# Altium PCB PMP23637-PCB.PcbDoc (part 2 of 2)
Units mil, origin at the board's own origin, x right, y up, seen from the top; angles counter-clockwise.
Board outline 3000 x 2000 mil, 6 copper layers (Top Layer, Layer 2, Signal Layer 3, Signal Layer 4, Layer 5, Bottom Layer), stack 61.712 mil thick; 143 components, 52 nets, 318 pads, 582 vias.
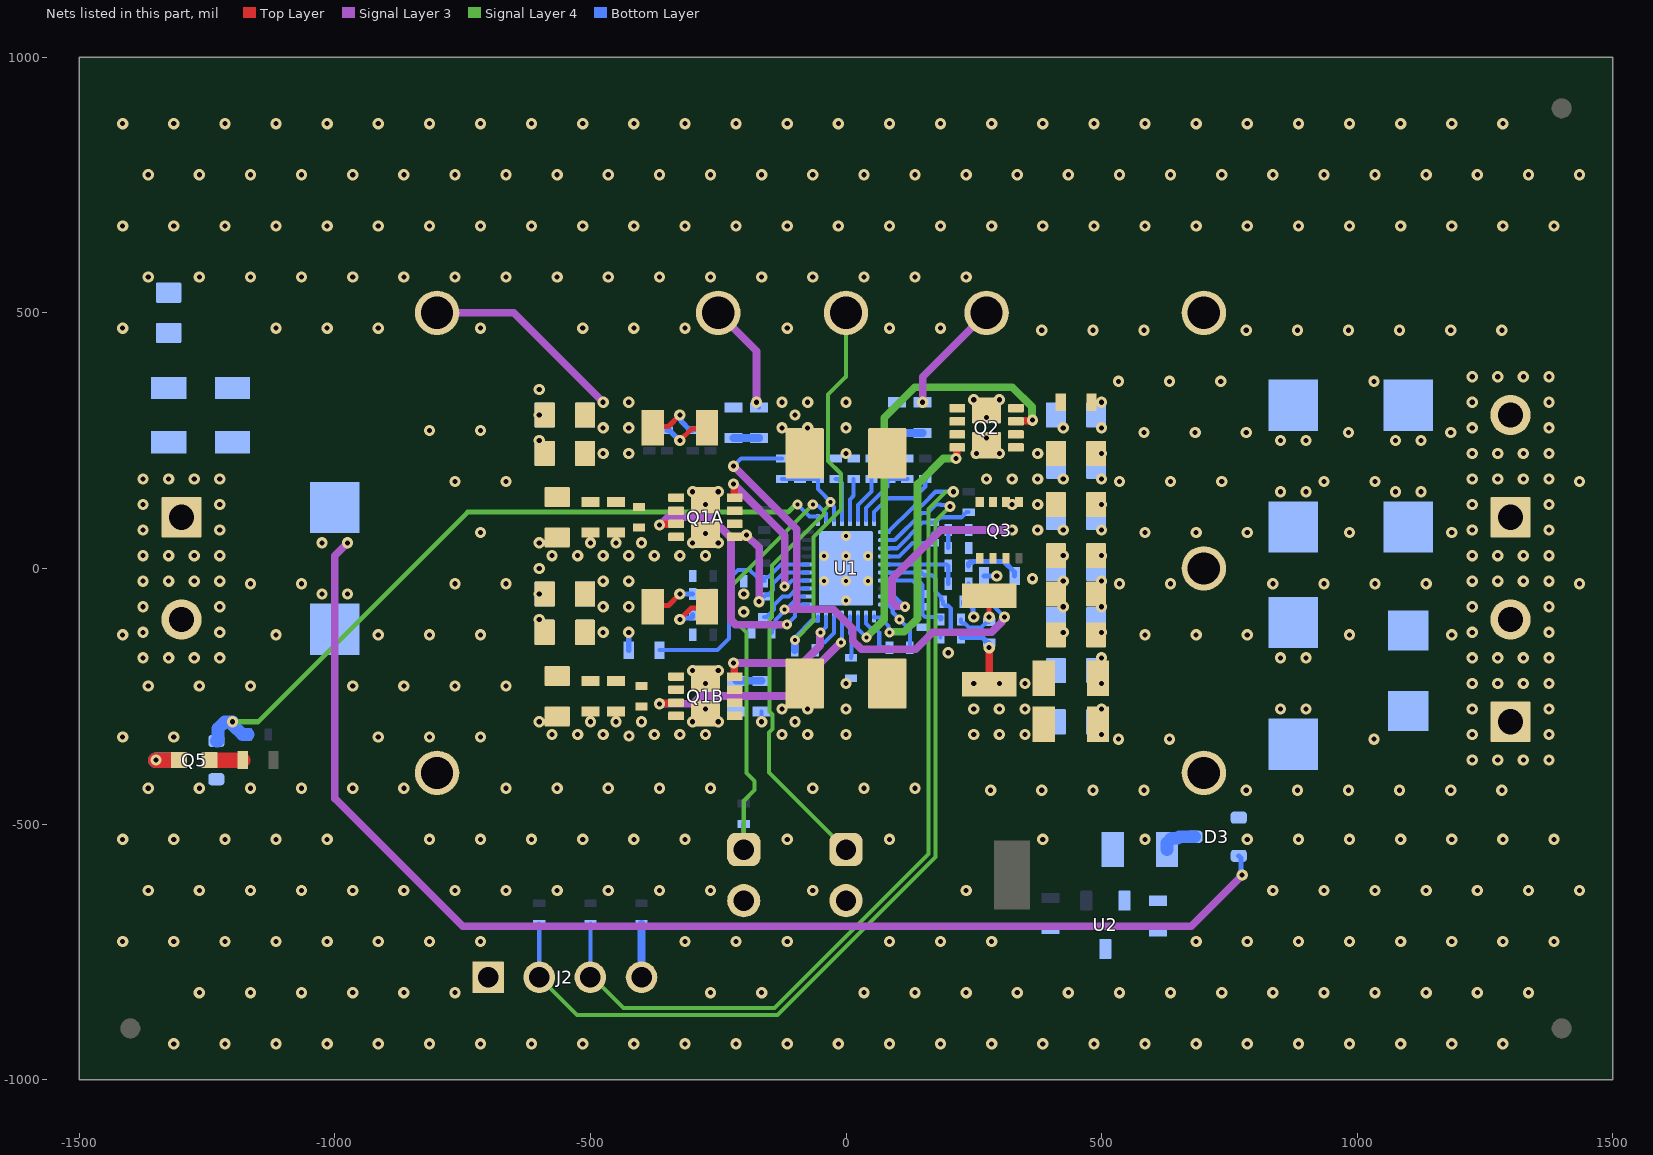
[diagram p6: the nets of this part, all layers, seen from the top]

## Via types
v1: diameter 22, hole 10, Top Layer to Bottom Layer, tented both sides, 560 vias
v2: diameter 19.68, hole 7.87, Top Layer to Bottom Layer, tented both sides, 22 vias

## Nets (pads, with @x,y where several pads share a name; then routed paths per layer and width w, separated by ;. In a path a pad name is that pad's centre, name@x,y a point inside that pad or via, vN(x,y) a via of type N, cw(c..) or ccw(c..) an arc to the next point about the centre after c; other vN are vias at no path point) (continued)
BTST1_A: C48.1 U1.3 | length 113.6
  Bottom Layer w8: C48.1@-160,-95 -155.5,-95 -141,-80.5 -141,-71.3 -124.54,-54.84 -111.78,-54.84 -96.31,-39.37 U1.3@-74.8,-39.37
BTST1_B: C44.1 U1.34 | length 85
  Bottom Layer w8: C44.1@-60,-160 -60,-155.5 -49.34,-144.84 -41.78,-144.84 -23.62,-126.68 U1.34@-23.62,-94.49
BTST2: C39.1 U1.30 | length 93.1
  Bottom Layer w8: U1.30@39.37,-94.49 39.43,-94.55 39.43,-107.54 48.19,-116.3 56.3,-116.3 65,-125 65,-150.31 69.69,-155 C39.1@85,-155
CELL_BATPRESZ: R6.2 R7.1 U1.23 | length 161.4
  Bottom Layer w8: U1.23@74.8,7.87 197.13,7.87 R6.2@200,5 R7.1@200,-30
CHRG_OK: Q5.1 R28.2 U1.11 | length 1448
  Signal Layer 4 w10: v1(-1200,-300) -1150,-300 -740,110 -291.11,110 -284.11,103 -265.89,103 -258.89,110 -113.25,110 -98.25,125 v2(-95,125)
  Bottom Layer w8: v2(-95,125) -71.18,101.18 -55.18,101.18 -55.12,101.12 U1.11@-55.12,94.49
  Bottom Layer w25: Q5.1@-1231.69,-337.6 -1229.13,-337.6 -1228.44,-336.91 -1228.44,-313.44 -1215,-300 v1(-1200,-300) -1200,-305.86 -1180.86,-325 R28.2@-1170,-325
CMPIN_TR: R4.2 R5.2 R10.2 U1.22 | length 191.9
  Bottom Layer w8: U1.22@74.8,23.62 103.62,23.62 130,50 R10.2@170,50 170,67.81 174.69,72.5 197.5,72.5 R4.2@200,75 R5.2@200,40
CMPOUT: R3.1 R10.1 U1.21 | length 194.5
  Bottom Layer w8: U1.21@74.8,39.37 99.37,39.37 150,90 174.5,90 184.5,100 225.5,100 235.5,110 R3.1@240,110
EN_OTG: JP1.1 R17.1 U1.12 | length 864.9
  Signal Layer 4 w8: JP1.1@-200,-550 -200,-454.7 -179,-433.7 -179,-416.3 -195,-400.3 -195,-125 -225,-95 -225,-35 v2(-65,125)
  Bottom Layer w8: JP1.1@-200,-550 R17.1@-200,-500 ; v2(-65,125) -62.32,122.32 -54.21,122.32 -39.43,107.54 -39.43,94.55 U1.12@-39.37,94.49
HIDRV1_A: Q1A.8 U1.4 | length 317.8
  Top Layer w15: v1(-220,165) -218.86,163.86 -218.86,139.15 -218.09,138.39 Q1A.8@-217.72,138.39
  Signal Layer 3 w15: v1@-219.1,164.1 -120,65 v2(-120,-35)
  Bottom Layer w8: v2(-120,-35) -116.84,-35 -105.46,-23.62 U1.4@-74.8,-23.62
HIDRV1_B: Q1B.8 U1.35 | length 272.2
  Top Layer w15: v1(-220,-185) -218.86,-186.14 -218.86,-210.85 -218.09,-211.61 Q1B.8@-217.72,-211.61
  Signal Layer 3 w15: v1(-220,-185) -85,-185 -50.9,-150.9 -50.9,-125.9 v2(-50,-125)
  Bottom Layer w8: v2(-50,-125) -39.37,-114.37 U1.35@-39.37,-94.49
HIDRV2: Q2.8 U1.29 | length 497.5
  Top Layer w15: v1(215,215) 216.34,216.34 216.34,235.85 217.11,236.61 Q2.8@217.72,236.61
  Signal Layer 4 w15: v2(85,-125) 85.9,-124.1 113.91,-124.1 140,-98.01 140,165 190,215 v1(215,215)
  Bottom Layer w8: U1.29@55.12,-94.49 55.12,-96.37 55.18,-96.43 66.43,-96.43 82.76,-112.76 82.76,-122.76 v2(85,-125)
IADPT: C43.1 U1.14 | length 88.2
  Bottom Layer w8: C43.1@-20,175 -15.5,175 -7.87,167.37 U1.14@-7.87,94.49
IBAT: C41.1 U1.15 | length 83.5
  Bottom Layer w8: U1.15@7.87,94.49 7.87,135.01 15,142.14 C41.1@15,175
ILIM_HIZ: C45.1 JP2.1 R15.1 R16.2 U1.13 | length 961.2
  Signal Layer 4 w8: v2(-30.14,130.16) -30.14,127 -43.42,113.72 -43.42,106.89 -145,5.3 -145,-95.3 -150,-100.3 -150,-279.7 -144,-285.7 -144,-314.3 -151,-321.3 -151,-399 JP2.1@0,-550
  Bottom Layer w8: R16.2@-125,175 R15.1@-90,175 C45.1@-55,175 -55,155.02 -27.91,127.92 -27.91,124.76 -23.62,120.48 U1.13@-23.62,94.49
LODRV1_A: Q1A.3 U1.1 | length 533.5
  Top Layer w15: v1(-365,85) -363.56,86.44 -333.05,86.44 Q1A.3@-332.28,87.2
  Signal Layer 3 w15: v1(-365,85) -363.73,85 -348.73,100 -265,100 -225,60 -225,-101.21 -216.21,-110 v2(-115,-110)
  Bottom Layer w8: v2(-115,-110) -99.38,-94.38 -99.38,-84.38 -85.87,-70.87 U1.1@-74.8,-70.87
LODRV1_B: Q1B.3 U1.33 | length 489.7
  Top Layer w15: v1(-365,-265) -363.56,-263.56 -333.05,-263.56 Q1B.3@-332.28,-262.8
  Signal Layer 3 w15: v1(-365,-265) -299.65,-265 -284.15,-249.5 -114.5,-249.5 v2(-10,-145)
  Bottom Layer w8: v2(-10,-145) -7.87,-142.87 U1.33@-7.87,-94.49
LODRV2: Q2.3 U1.31 | length 881.4
  Top Layer w15: Q2.3@332.28,287.8 333.05,288.56 361.67,288.56 363.11,290 v1(365,290)
  Signal Layer 4 w15: v2(40,-135) 75,-100 75,295 134.5,354.5 325.5,354.5 363.81,316.19 363.81,291.19 v1(365,290)
  Bottom Layer w8: U1.31@23.62,-94.49 23.62,-118.62 v2(40,-135)
MODE: R14.2 U1.16 | length 91.4
  Bottom Layer w8: U1.16@23.62,94.49 23.62,123.71 50,150.09 R14.2@50,175
NetC6_1: C6.1 C8.1 C10.1 C12.1 Q1B.1 Q1B.2 Q1B.9 R22.2 RAC_B.2 | length 95.3
  Top Layer w10: v1(-325,-100) -302.65,-77.65 -274.5,-77.65 RAC_B.2@-271.85,-75
  Bottom Layer w10: v1(-325,-100) -321.75,-100 -318.75,-97 -302.5,-97 -300,-94.5 R22.2@-300,-90
  other v1: -275,-225 -300,-200 -250,-200
NetC24_2: C24.2 R2.1 U2.2
NetC36_2: C36.2 R13.2 | length 50
  Bottom Layer w15: R13.2@100,265 C36.2@150,265
NetC49_2: C49.2 R18.2 | length 50
  Bottom Layer w15: R18.2@-220,255 C49.2@-170,255
NetC52_2: C52.2 R19.2 | length 50
  Bottom Layer w15: R19.2@-215,-220 -210,-220 C52.2@-165,-220
NetC62_1: C62.1 R29.1 R30.1
NetD1_1: D1.1 R1.1 | length 65.5
  Top Layer w30: D1.1@-1245.47,-375 R1.1@-1180,-375
NetD1_2: D1.2 Q5.3 | length 77.2
  Top Layer w30: v1(-1350,-375) D1.2@-1304.53,-375
  Bottom Layer w30: v1(-1350,-375) Q5.3@-1318.31,-375
NetD3_3: D3.3 R2.2 | length 71.4
  Bottom Layer w25: R2.2@628.15,-550 628.15,-537.2 637.3,-528.05 648.9,-528.05 651.95,-525 D3.3@681.69,-525
NetJ2_4: J2.4 R25.2 | length 105
  Bottom Layer w15: J2.4@-400,-800 R25.2@-400,-695
PGND: C1.2 C2.2 C3.2 C4.2 C5.2 C6.2 C7.2 C8.2 C9.2 C10.2 C11.2 C12.2 C13.2 C14.2 C15.2 C16.2 C17.2 C18.2 C19.2 C20.2 C21.2 C22.2 C23.2 C24.1 C25.2 C26.2 C27.2 C28.2 C29.2 C30.2 C31.2 C32.1 C33.2 C35.2 C38.2 C40.2 C41.2 C42.1 C43.2 C45.2 C50.2 C51.2 C53.2 C54.2 C55.2 C56.2 C57.2 C58.2 C59.2 C60.2 C61.2 C62.2 D2.2 J1.2 J2.1 J3.1 J4.2 JP1.2 JP2.2 Q1A.4 Q1A.10 Q1B.4 Q1B.10 Q2.4 Q2.10 Q5.2 R5.1 R6.1 R12.2 R13.1 R14.1 R15.2 R18.1 R19.1 TP2.1 TP9.1 U1.37 U2.3 | length 156.4
  Bottom Layer w10: C35.2@230,-65 230,-69.5 232.5,-72 242.29,-72 248.15,-77.86 248.15,-93.15 v1(250,-95) ; R6.1@240,5 240,9.5 242.5,12 247,12 248.5,13.5 309,13.5 330,-7.5 C33.2@330,-15
  other v1: -1315,-930 -1215,-930 -1115,-930 -1015,-930 -915,-930 -815,-930 -715,-930 -615,-930 -515,-930 -415,-930 -315,-930 -215,-930 -115,-930 -15,-930 85,-930 185,-930 285,-930 385,-930 485,-930 585,-930 685,-930 785,-930 885,-930 985,-930 1085,-930 1185,-930 1285,-930 -1265,-830 -1165,-830 -1065,-830 -965,-830 -865,-830 -765,-830 -265,-830 -165,-830 35,-830 135,-830 235,-830 335,-830 435,-830 535,-830 635,-830 735,-830 835,-830 935,-830 1035,-830 1135,-830 1235,-830 1335,-830 -1415,-730 -1315,-730 -1215,-730 -1115,-730 -1015,-730 -915,-730 -815,-730 -715,-730 -315,-730 -215,-730 -115,-730 85,-730 185,-730 285,-730 685,-730 785,-730 885,-730 985,-730 1085,-730 1185,-730 1285,-730 1385,-730 -1365,-630 -1265,-630 -1165,-630 -1065,-630 -965,-630 -865,-630 -765,-630 -665,-630 -565,-630 -465,-630 -365,-630 -265,-630 -65,-630 235,-630 835,-630 935,-630 1035,-630 1135,-630 1235,-630 1335,-630 1435,-630 -1415,-530 -1315,-530 -1215,-530 -1115,-530 -1015,-530 -815,-530 -715,-530 -615,-530 -515,-530 -415,-530 -315,-530 -115,-530 85,-530 385,-530 585,-530 785,-530 885,-530 985,-530 1085,-530 1185,-530 1285,-530 1385,-530 -1365,-430 -1265,-430 -1165,-430 -1065,-430 -965,-430 -865,-430 -665,-430 -565,-430 -465,-430 -365,-430 -265,-430 -65,-430 35,-430 135,-430 -1415,-330 -1315,-330 -915,-330 -815,-330 -715,-330 -424.33,-327.74 -575,-325 -525,-325 -475,-325 -375,-325 -325,-325 -275,-325 0,-325 500,-325 -600,-300 -500,-300 -450,-300 -400,-300 -300,-300 -250,-300 -275,-275 0,-275 500,-275 -1365,-230 -1265,-230 -1165,-230 -965,-230 -865,-230 -765,-230 -665,-230 0,-225 500,-225 -1375,-175 -1325,-175 -1275,-175 -1225,-175 500,-175 850,-175 900,-175 1225,-175 1275,-175 1325,-175 1375,-175 200,-165 -1415,-130 -1115,-130 -915,-130 -815,-130 -715,-130 585,-130 685,-130 785,-130 985,-130 1185,-130 -1375,-125 -1225,-125 500,-125 1225,-125 1375,-125 -600,-100 -200,-85 -1375,-75 -1225,-75 500,-75 1225,-75 1375,-75 -1025,-50 -975,-50 -600,-50 -200,-50 -1165,-30 -1065,-30 -765,-30 -665,-30 535,-30 635,-30 835,-30 935,-30 1035,-30 1135,-30 1435,-30 -1375,-25 -1325,-25 -1275,-25 -1225,-25 500,-25 1225,-25 1275,-25 1325,-25 1375,-25 365,-20 -600,0 -575,25 -525,25 -475,25 -425,25 -375,25 -325,25 -275,25 500,25 1225,25 1275,25 1325,25 1375,25 -600,50 -500,50 -450,50 -400,50 -300,50 -250,50 -275,68 -715,70 585,70 685,70 785,70 985,70 1185,70 500,75 1225,75 1375,75 500,125 1225,125 1375,125 850,150 900,150 1075,150 1125,150 -765,170 -665,170 535,170 635,170 735,170 935,170 1035,170 1435,170 500,175 1225,175 1275,175 1325,175 1375,175 0,225 500,225 -600,250 -815,270 -715,270 0,275 500,275 275,295 -600,300 0,325 500,325 250,330 300,330 -600,350 -1415,470 -1115,470 -1015,470 -915,470 -715,470 -515,470 -415,470 -315,470 -115,470 85,470 185,470 -1365,570 -1265,570 -1165,570 -1065,570 -965,570 -865,570 -765,570 -665,570 -565,570 -465,570 -365,570 -265,570 -165,570 -65,570 35,570 135,570 235,570 -1415,670 -1315,670 -1215,670 -1115,670 -1015,670 -915,670 -815,670 -715,670 -615,670 -515,670 -415,670 -315,670 -215,670 -115,670 -15,670 85,670 185,670 285,670 385,670 485,670 585,670 685,670 785,670 885,670 985,670 1085,670 1185,670 1285,670 1385,670 -1365,770 -1265,770 -1165,770 -1065,770 -965,770 -865,770 -765,770 -665,770 -565,770 -465,770 -365,770 -265,770 -165,770 -65,770 35,770 135,770 235,770 335,770 435,770 535,770 635,770 735,770 835,770 935,770 1035,770 1135,770 1235,770 1335,770 1435,770 -1415,870 -1315,870 -1215,870 -1115,870 -1015,870 -915,870 -815,870 -715,870 -615,870 -515,870 -415,870 -315,870 -215,870 -115,870 -15,870 85,870 185,870 285,870 385,870 485,870 585,870 685,870 785,870 885,870 985,870 1085,870 1185,870 1285,870
  other v2: 0,-62.99 -43.31,-24.61 0,-24.61 43.31,-24.61 -43.31,24.61 0,24.61 43.31,24.61 0,62.99
PROCHOT: R11.2 U1.18 | length 151.2
  Bottom Layer w8: U1.18@55.12,94.49 55.12,110.12 82.2,137.2 132.2,137.2 155,160 R11.2@155,175
PSYS: C40.1 R12.1 U1.17 | length 134.8
  Bottom Layer w8: U1.17@39.37,94.49 39.37,118.3 81.26,160.19 81.26,171.5 C40.1@84.76,175 ; C40.1@85,175 C40.1@84.76,175 ; R12.1@120,175 C40.1@84.76,175
REGNA: C51.1 R7.2 R16.1 U1.2 | length 1140.3
  Signal Layer 3 w15: v1(-220,200) -96.66,76.66 -96.66,-79.85 ; v2@-120,-79.31 v2(-120,-80) -96.8,-80 -25,-80 13.34,-118.34 13.34,-141.35 30.33,-158.34 136.66,-158.34 170,-125 284.65,-125 304.5,-105.15 304.5,-102.39 310,-96.89 v1(310,-95)
  Bottom Layer w8: v1(-220,200) -205,215 R16.1@-125,215 ; C51.1@-145,-125 -145,-120.5 -138,-113.5 -138,-100.84 -120,-82.84 v2(-120,-80) -117.14,-80 -92.32,-55.18 U1.2@-82.61,-55.18 ; R7.2@240,-30 240,-34.5 270.58,-65.08 280.08,-65.08 v1(310,-95)
REGNB: C42.2 U1.32 | length 82.2
  Bottom Layer w8: U1.32@7.87,-94.49 7.87,-127.67 9.84,-129.64 9.84,-137.9 10.93,-138.99 10.93,-171.5 10,-172.43 C42.2@10,-175
SCL: J2.2 R27.1 U1.20 | length 1895.1
  Signal Layer 4 w8: J2.2@-600,-800 -526.2,-873.8 -134,-873.8 175,-564.8 175,92.68 v1@203.13,120.81
  Bottom Layer w8: J2.2@-600,-800 R27.1@-600,-695 ; U1.20@74.8,55.12 74.87,55.18 95.38,55.18 148.51,108.31 159.52,108.31 176.21,125 184.66,125 185.64,124.02 200.98,124.02 v1(203.66,121.34)
SDA: J2.3 R26.1 U1.19 | length 1813.6
  Signal Layer 4 w8: J2.3@-500,-800 -495,-800 -435.2,-859.8 -139.8,-859.8 161,-559 161,116 194.24,149.24 209.24,149.24 v1(210,150)
  Bottom Layer w8: J2.3@-500,-800 R26.1@-500,-695 ; U1.19@82.61,70.93 131.88,120.2 134.88,123.2 148.41,123.2 175.21,150 v1(210,150)
SRN: C35.1 C37.2 R9.1 U1.24 | length 251.3
  Bottom Layer w8: U1.24@74.8,-7.87 147.87,-7.87 152.74,-12.74 167.74,-12.74 175,-20 175,-45 186.5,-56.5 186.5,-61.5 C35.1@190,-65 190,-69.5 193.5,-73 199.81,-73 205,-78.19 205,-121.81 199.81,-127 188.5,-127 185,-130.5 R9.1@185,-135
SRP: C37.1 C38.1 R8.1 U1.25 | length 180.8
  Bottom Layer w8: U1.25@74.8,-23.62 129.98,-23.62 133.86,-27.5 145.31,-27.5 150,-32.19 C37.1@150,-50 C38.1@150,-75 150,-90 155,-95 186.5,-95 186.5,-98.5 R8.1@185,-100
SW1_A: C48.2 C49.1 L1_A.1 Q1A.5 Q1A.6 Q1A.7 TP3.1 U1.5 | length 470.9
  Signal Layer 3 w15: TP3.1@-250,500 -175,425 v1(-175,325) ; v1(-195,65) -170,40 v1(-170,-65)
  Bottom Layer w8: v1(-175,325) -175,320 C49.1@-170,315 ; C48.2@-160,-55 -156.5,-51.5 -151.5,-51.5 -142.5,-42.5 -142.5,-29.44 -120.94,-7.87 U1.5@-74.8,-7.87
  other v1: -125,275 -75,275 -100,300 -125,325 -75,325
SW1_B: C44.2 C52.1 L1_B.1 Q1B.5 Q1B.6 Q1B.7 TP4.1 U1.36 | length 804.1
  Signal Layer 4 w8: v2(-100,-140) -63.23,-103.23 -63.23,61.77 -10.16,114.84 -10.16,185.16 -35,210 -35,340 0,375 TP4.1@0,500
  Bottom Layer w8: v1(-165,-300) C52.1@-165,-280 ; v2@-97.1,-132.1 -67.3,-102.3 -55.18,-102.3 -55.12,-102.24 U1.36@-55.12,-94.49
  Bottom Layer w15: C44.2@-100,-160 v2(-100,-140)
  other v1: -125,-325 -75,-325 -100,-300 -125,-275 -75,-275
SW2: C36.1 C39.2 L1_A.2 L1_B.2 Q2.5 Q2.6 Q2.7 TP5.1 U1.28 | length 336.2
  Signal Layer 3 w15: v1(150,325) 150,375 TP5.1@275,500
  Bottom Layer w8: U1.28@74.8,-70.87 82.55,-70.87 91.45,-79.77 91.45,-86.45 v2(105,-100) 125,-120 125,-154.89 C39.2@125,-155
VBAT: C13.1 C14.1 C23.1 C34.2 D2.1 D3.1 J4.1 R9.2 RSR.2 TP10.1 | length 131.7
  Top Layer w15: RSR.2@280,-226.61 v1(280,-155)
  Bottom Layer w10: R9.2@225,-135 267.14,-135 273,-140.86 273,-142.5 275.5,-145 C34.2@280,-145
  other v1: 283,-434 383,-434 483,-434 583,-434 783,-434 883,-434 983,-434 1083,-434 1183,-434 1283,-434 1225,-375 1275,-375 1325,-375 1375,-375 533,-334 633,-334 1033,-334 250,-325 300,-325 350,-325 1225,-325 1375,-325 250,-275 300,-275 350,-275 850,-275 900,-275 1225,-275 1375,-275 250,-225 300,-225 350,-225 1225,-225 1275,-225 1325,-225 1375,-225
VBAT_R: C33.1 C34.1 Q3.1 Q3.2 Q3.3 R8.2 RSR.1 | length 139.2
  Top Layer w10: v1(280,-95) RSR.1@280,-53.39
  Bottom Layer w8: R8.2@225,-100 225,-104.5 228.5,-108 233,-108 241,-116 264.5,-116 275.5,-105 C34.1@280,-105 ; v1@276.21,-95 v1(280,-95)
  Bottom Layer w10: C33.1@270,-15 v1(295,-15)
VBUS: C50.1 R20.1 U1.6 | length 447.4
  Bottom Layer w8: R20.1@-365,-160 -251.36,-160 -228.5,-137.14 -228.5,-19.86 -211.64,-3 -188.36,-3 -174.36,-17 -163.5,-17 C50.1@-160,-20.5 ; C50.1@-160,-25 C50.1@-160,-20.5 ; U1.6@-74.8,7.87 -127.13,7.87 -152,-17 -156.5,-17 C50.1@-160,-20.5
VIN: C1.1 C2.1 C3.1 C4.1 C57.1 C58.1 C59.1 C60.1 C61.1 D3.2 J1.1 R20.2 R21.2 R23.2 R29.2 R30.2 RAC_A.1 RAC_B.1 TP1.1 | length 3098.2
  Top Layer w10: RAC_B.1@-378.15,-75 -375.5,-72.35 -347.35,-72.35 v1(-325,-50) ; RAC_A.1@-378.15,275 -375.5,277.65 -347.35,277.65 v1(-325,300)
  Signal Layer 3 w15: v1(-975,50) -1000,25 -1000,-450 -750,-700 675,-700 v1(775,-600) ; TP1.1@-800,500 -650,500 v1(-475,325)
  Bottom Layer w10: R20.2@-425,-160 v1(-425,-125) ; v1(-325,-50) R21.2@-300,-50 ; v1(-325,300) -322.7,297.7 -322.7,288.2 -304.5,270 R23.2@-300,270 ; D3.2@768.31,-562.4 772.7,-566.8 772.7,-597.7 v1(775,-600)
  other v1: -475,-125 -475,-75 -425,-75 -475,-25 -425,-25 -1375,25 -1325,25 -1275,25 -1225,25 -1025,50 -1375,75 -1225,75 -1375,125 -1225,125 -1375,175 -1325,175 -1275,175 -1225,175 -475,225 -425,225 -475,275 -425,275 -425,325
VIN_R_A: C5.1 C7.1 C9.1 C11.1 Q1A.1 Q1A.2 Q1A.9 R24.2 RAC_A.2 | length 96.8
  Top Layer w10: v1(-325,250) -302.65,272.35 -274.5,272.35 RAC_A.2@-271.85,275
  Bottom Layer w10: R24.2@-350,270 -345.5,270 -325.5,250 v1(-325,250)
  other v1: -275,125 -300,150 -250,150
VSYS: C15.1 C16.1 C17.1 C18.1 C19.1 C20.1 C21.1 C22.1 C25.1 C26.1 C27.1 C28.1 C29.1 C30.1 C31.1 J3.2 Q2.1 Q2.2 Q2.9 Q3.5 Q3.6 Q3.7 Q3.8 R4.1 TP8.1 U1.27 | length 482
  Signal Layer 3 w15: v2(115,-75) 113.84,-73.84 98.79,-73.84 90,-65.05 90,-20 185,75 v1(325,75)
  Bottom Layer w8: U1.27@74.8,-55.12 95.12,-55.12 v2(115,-75)
  Bottom Layer w15: R4.1@240,75 v1(325,75)
  other v1: 425,-125 425,-75 425,-25 425,25 375,75 425,75 325,125 375,125 275,175 325,175 375,175 425,175 255,225 300,225 375,225 1225,225 1275,225 1325,225 1375,225 850,250 900,250 1075,250 1125,250 275,255 583,266 683,266 783,266 983,266 1183,266 425,275 1225,275 1375,275 1225,325 1375,325 533,366 633,366 733,366 1033,366 1225,375 1275,375 1325,375 1375,375 383,466 483,466 583,466 783,466 883,466 983,466 1083,466 1183,466 1283,466
pads on no net: FID1.1 FID2.1 FID3.1 FID4.1 FID5.1 FID6.1 H1.0 H2.0 H3.0 H4.0 LBL1.0 SH-JP1.0 SH-JP2.0

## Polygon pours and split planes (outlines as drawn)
VSYS on Top Layer "VSYS_L01_P183" (solid, pour order 183): 1425,575 350,575 350,200 1425,200
PGND on Top Layer "PGND_L01_P157" (solid, remove dead copper, pour order 157): 452.74,375 452.74,-375 527.74,-375 527.74,375
VBAT on Top Layer "VBAT_L01_P197" (solid, pour order 197): 1425,-200 962.5,-200 225,-200 225,-500 1425,-500
SW1_B on Top Layer "SW1_B_L01_P192" (solid, remove dead copper, pour order 192): -100,-100 -33.07,-166.93 -33.07,-375 -226.15,-375 -226.15,-100
VSYS on Top Layer "VSYS_L01_P185" (solid, remove dead copper, pour order 185): 450,-150 375,-150 375,50 225,50 225,150 250,150 250,275 375,275 375,375 450,375
VIN on Top Layer "VIN_L01_P189" (solid, remove dead copper, pour order 189): -550,375 -550,200 -350,200 -350,375
VIN on Top Layer "VIN_L01_P187" (solid, remove dead copper, pour order 187): -550,0.2 -550,-149.8 -350,-149.8 -350,0.2
VBAT on Top Layer "VBAT_L01_P184" (solid, remove dead copper, pour order 184): 225,-175 225,-375 440,-375 440,-175
VBAT_R on Top Layer "VBAT_R_L01_P190" (solid, remove dead copper, pour order 190): 225,25 225,-75 350,-75 350,25
SW2 on Top Layer "SW2_L01_P191" (solid, remove dead copper, pour order 191): 35,-375 35,375 225,375 225,175 200,175 200,-375
SW1_A on Top Layer "SW1_A_L01_P194" (solid, remove dead copper, pour order 194): -226.15,375 -226.15,51.15 -148.85,51.15 -35,165 -35,375
NetC6_1 on Top Layer "NETC6_1_L01_P195" (solid, remove dead copper, pour order 195): -300,0 -300,-160 -600,-160 -600,-250 -250,-250 -250,0
VIN_R_A on Top Layer "VIN_R_A_L01_P196" (solid, remove dead copper, pour order 196): -300,375 -300,190 -600,190 -600,100 -250,100 -250,375
PGND on Top Layer "PGND_L01_P198" (solid, remove dead copper, pour order 198): -1500,1000 -1500,-1000 1500,-1000 1500,1000
SW1_B on Bottom Layer "SW1_B_L06_P156" (solid, remove dead copper, pour order 156): -50,-375 -50,-250 -200,-250 -200,-375
SW1_A on Bottom Layer "SW1_A_L06_P174" (solid, remove dead copper, pour order 174): -200,375 -50,375 -50,250 -150,250 -200,250
3V3 on Bottom Layer "3V3_L06_P178" (solid, remove dead copper, pour order 178): 374.99,-600 374.99,-674.99 485,-675 485,-600
NetC24_2 on Bottom Layer "NETC24_2_L06_P179" (solid, remove dead copper, pour order 179): 490.2,-510 490.2,-674.56 645,-674.56 645,-600 560,-600 560,-510
VSYS on Bottom Layer "VSYS_L06_P201" (solid, pour order 201): 1425,575 350,575 350,200 1425,200
VBAT on Bottom Layer "VBAT_L06_P182" (solid, pour order 182): 1425.57,-201.65 963.07,-201.65 200,-201.65 200,-501.65 1425.57,-501.65
PGND on Bottom Layer "PGND_L06_P181" (solid, remove dead copper, pour order 181): 450,375 450,-375 525,-375 525,375
VIN on Bottom Layer "VIN_L06_P188" (solid, pour order 188): -875,0 -1500,0 -1500,275 -875,275
VSYS on Bottom Layer "VSYS_L06_P176" (solid, remove dead copper, pour order 176): 175,375 175,200 275,100 275,25 375,25 375,-375 450,-375 450,375
VIN on Bottom Layer "VIN_L06_P193" (solid, remove dead copper, pour order 193): -550,0 -550,-150 -425,-150 -425,0
VIN on Bottom Layer "VIN_L06_P199" (solid, remove dead copper, pour order 199): -550,350 -550,200 -425,200 -425,350
PGND on Bottom Layer "PGND_L06_P203" (solid, remove dead copper, pour order 203): -1501.41,1005 1498.59,1005 1498.59,-995 -1501.41,-995
NetC62_1 on Bottom Layer "NETC62_1_L06_P200" (solid, pour order 200): -1375,500 -1375,300 -1150,300 -1150,500
CMPIN_TR on Bottom Layer "CMPIN_TR_L06_P204" (solid, pour order 204): 275,-85 275,-120 300,-120 300,-160 395,-160 395,-85
PGND on Signal Layer 4 "PGND_L04_P127" (solid, remove dead copper, pour order 127): 1512.14,-1001.98 1512.14,1002.7 -1487.86,1002.7 -1487.86,-997.3
PGND on Signal Layer 3 "PGND_L03_P110" (solid, remove dead copper, pour order 110): -1500,1000 1500,1000 1500,-1000 -1500,-1000
3V3 on Layer 5 (split plane): 244.9,-147.89 196.4,-196.4 195.29,-198.05 194.9,-200 194.9,-500 195.29,-501.95 196.4,-503.6 198.05,-504.71 200,-505.1 1479.9,-505.1 1479.9,-979.9 -1479.9,-979.9 -1479.9,-355.1 -1250,-355.1 -512.15,-355.1 -488.64,-378.6 -486.99,-379.71 -485.04,-380.1 125,-380.1 126.95,-379.71 128.6,-378.6 129.71,-376.95 130.1,-375 130.1,194.9 244.9,194.9
VIN on Layer 5 (split plane): -380.1,-169.9 -1479.9,-169.9 -1479.9,369.9 -380.1,369.9
VBAT on Layer 5 (split plane): 1479.9,-494.9 205.1,-494.9 205.1,-205.1 1479.9,-205.1
VSYS on Layer 5 (split plane): 1394.9,205.1 450,205.1 448.05,204.71 446.4,203.6 445.29,201.95 444.9,200 444.9,-194.9 212.31,-194.9 253.6,-153.6 254.71,-151.95 255.1,-150 255.1,200 254.71,201.95 253.6,203.6 251.95,204.71 250,205.1 130.1,205.1 130.1,394.9 1394.9,394.9
PGND on Layer 5 (split plane): 1479.9,-194.9 455.1,-194.9 455.1,194.9 1400,194.9 1401.95,195.29 1403.6,196.4 1404.71,198.05 1405.1,200 1405.1,400 1404.71,401.95 1403.6,403.6 1401.95,404.71 1400,405.1 125,405.1 123.05,404.71 121.4,403.6 120.29,401.95 119.9,400 119.9,200 119.9,-369.9 -482.93,-369.9 -506.43,-346.4 -508.09,-345.29 -510.04,-344.9 -1250,-344.9 -1479.9,-344.9 -1479.9,-180.1 -375,-180.1 -373.05,-179.71 -371.4,-178.6 -370.29,-176.95 -369.9,-175 -369.9,375 -370.29,376.95 -371.4,378.6 -373.05,379.71 -375,380.1 -1479.9,380.1 -1479.9,979.9 1479.9,979.9
PGND on Layer 2 (split plane): 1479.9,-979.9 -1479.9,-979.9 -1479.9,979.9 1479.9,979.9

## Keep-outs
Keep-Out Layer:
  lines w10: -1485,-985 1485,-985 1485,985 -1485,985 -1485,-985
  text ".Layer_Name" at -1448,-2958.49 h60

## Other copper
Top Layer:
  rectangle net VIN: -1400,0 -1200,200
  text ".Layer_Name" at -1448,-2958.49 h60
Signal Layer 3:
  text ".Layer_Name" at -1448,-2958.49 h60
Signal Layer 4:
  text ".Layer_Name" at -1448,-2958.49 h60
Bottom Layer:
  text ".Layer_Name" at -1448,-2958.49 h60
Layer 2 (plane layer: these items are gaps in the copper):
  text ".Layer_Name" at -1440,-2955 h60
Layer 5 (plane layer: these items are gaps in the copper):
  lines w10: -1500,-350 -1250,-350 ; -1500,-175 -375,-175 -375,375 -1500,375 ; 450,-199.65 450,200 1400,200 1400,400 125,400 125,200 ; 1495.59,-195.59 1491.18,-200 200,-200 ; 1500,-500 200,-500 200,-200 ; -1250,-350 -1250,-350 ; -1250,-350 -510.04,-350 -485.04,-375 125,-375 125,200 ; 125,200 152.62,200 250,200 250,-150 200,-200
  text ".Layer_Name" at -1425,-2940 h60

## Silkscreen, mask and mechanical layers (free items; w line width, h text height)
Top Overlay:
  lines w5: -23,335 18,335 ; -22,-333 25,-333
  lines w10: -625,-385 525,-385 525,382 -625,382 -625,-385
  text "PMP23637 REVA" at -400,850 h100
  text "SW1_A" at -350,650 h60
  text "SW1_B" at -100,650 h60
  text "SW2" at 175,650 h60
  text "VIN" at -850,375 h60
  text "VSYS" at 650,375 h60
  text "VSYS" at 925,275 h60
  text "VIN" at -1075,75 h60
  text "PGND" at 925,75 h60
  text "PGND" at -1075,-125 h60
  text "PGND" at 625,-125 h60
  text "PGND" at 925,-150 h60
  text "CHG_OK" at -1345,-325 h60
  text "VBAT" at 925,-325 h60
  text "PGND" at -875,-525 h60
  text "VBAT" at 625,-525 h60
  text "EN_OTG" at -100,-700 h60 r90
  text "HIZ" at 100,-700 h60 r90
  text "GND" at -800,-750 h60
  text "SCL" at -650,-750 h60
  text "SDA" at -525,-750 h60
  text "3V3" at 275,-750 h60
  text "3V3" at -350,-825 h60
  text ".Layer_Name" at -1448,-2958.49 h60
Bottom Overlay:
  lines w5: -280,385 -265,370 -265,290 ; -150,-145 -140,-155 -140,-635 -125,-650 ; 140,-620 135,-615 135,-190 150,-175 150,-145 ; 160,490 180,470 180,325
  lines w10: -625,-375 525,-375 525,375 -625,375 -625,-375
  text ".Layer_Name" at -1448,-2958.49 h60
Top Paste:
  text ".Layer_Name" at -1448,-2958.49 h60
Bottom Paste:
  text ".Layer_Name" at -1448,-2958.49 h60
Top Solder:
  rectangle: -109.8,-375 -35,-150.59
  rectangle: 31.93,-375 106.73,-150.59
  rectangle: 31.93,145.59 106.73,370
  rectangle: -109.8,145.59 -35,370
  rectangle: 67,-296 163,-154
  rectangle: -163,-296 -67,-154
  rectangle: 67,154 163,296
  rectangle: -164,154 -67,296
  text ".Layer_Name" at -1448,-2958.49 h60
  text ".Layer_Name" at -1448,-2958.49 h60
Bottom Solder:
  text ".Layer_Name" at -1448,-2958.49 h60
Drill Guide:
  text ".Layer_Name" at -1448,-2958.49 h60
M1 Board Outline:
  the board outline again, w10
  text ".Layer_Name" at -1448,-2958.49 h60
M2 Board Dimensions:
  rectangle: -2025,-2375 -1900,-2250
  rectangle: -1900,-2500 -1525,-2375
  lines w7: -2025,-2375 -1025,-2375 ; -1900,-2500 -1900,-2250 ; -1775,-2500 -1775,-2250 ; -1525,-2500 -1525,-2250 ; -1275,-2500 -1275,-2250 ; -2025,-2500 -1025,-2500 -1025,-2250 -2025,-2250 -2025,-2500
  text ".Layer_Name" at -1448,-2958.49 h60
M3 3D STEP Top:
  text ".Layer_Name" at -1448,-2958.49 h60
M4 3D STEP Bottom:
  text ".Layer_Name" at -1448,-2958.49 h60
M5 Assembly Top:
  lines w10: -2317,-3030.17 4283,-3030.17 ; -2317,-2826.83 4285,-2826.83 ; -2317,-2623.5 -2317,-3233.5 1688,-3233.5 4285,-3233.5 4285,-2623.5 -2316.5,-2623.5 -2316.5,-3233.5 -741,-3233.5 ; 148,-3233.5 148,-2623.5 ; 1415,-2826.83 1415,-2623.5 ; 2255,-2826.83 2255,-2623.5 ; 2877,-3240 2877,-3037.17
  text "COMPONENTS MARKED 'DNP' SHOULD NOT BE POPULATED." at -871.5,-2418.5 h60
  text "ASSEMBLY VARIANT:" at -872,-2534 h60
  text ".VariantName" at 164,-2534 h60
  text "PCB VIEWED FROM TOP SIDE" at -2253.5,-2755.67 h60
  text "BOARD #:" at 223,-2755.67 h60
  text ".PRJ_Number" at 768.5,-2755.67 h60
  text "REV:" at 1613,-2755.67 h60
  text ".PCB_Rev" at 1904.5,-2755.67 h60
  text "SVN REV:" at 2451,-2755.67 h60
  text ".VersionControl_RevNumber" at 2957,-2755.67 h60
  text "TID #:" at 223,-2959 h60
  text ".TID" at 768.5,-2959 h60
  text "PLOT NAME =" at -2253.5,-3164.34 h60
  text ".plot_File_Name" at -1448,-3164.34 h60
  text "GENERATED    :" at 225,-3164.34 h60
  text ".Print_Date" at 1094.5,-3164.34 h60
  text ".Print_Time" at 1823.5,-3164.34 h60
  text "TEXAS INSTRUMENTS" at 3088,-3164.34 h60
M6 Assembly Bottom:
  lines w10: -2317.5,-2827.33 4284.5,-2827.33 ; -2315.5,-3030.67 4284.5,-3030.67 ; -909.5,-3240.5 -909.5,-3037.67 ; -287.5,-2827.33 -287.5,-2624 ; 552.5,-2827.33 552.5,-2624 ; 1819.5,-3234 1819.5,-2624 ; 2708.5,-3234 4284,-3234 4284,-2624 -2317.5,-2624 -2317.5,-3234 279.5,-3234 4284.5,-3234 4284.5,-2624
  text "COMPONENTS MARKED 'DNP' SHOULD NOT BE POPULATED." at 4077,-2418 h60
  text ".VariantName" at 3033,-2534 h60
  text "ASSEMBLY VARIANT:" at 4072,-2534 h60
  text ".VersionControl_RevNumber" at -989.5,-2756.17 h60
  text "SVN REV:" at -483.5,-2756.17 h60
  text ".PCB_Rev" at 63,-2756.17 h60
  text "REV:" at 354.5,-2756.17 h60
  text ".PRJ_Number" at 1199,-2756.17 h60
  text "BOARD #:" at 1744.5,-2756.17 h60
  text "PCB VIEWED FROM BOTTOM SIDE" at 4221,-2756.17 h60
  text ".TID" at 1199,-2959.5 h60
  text "TID #:" at 1744.5,-2959.5 h60
  text "TEXAS INSTRUMENTS" at -1120.5,-3164.84 h60
  text ".Print_Time" at 144,-3164.84 h60
  text ".Print_Date" at 873,-3164.84 h60
  text "GENERATED    :" at 1742.5,-3164.84 h60
  text ".plot_File_Name" at 3415.5,-3164.84 h60
  text "PLOT NAME =" at 4221,-3164.84 h60
M9 Title Sheet:
  drawing of 57 lines, arcs and shapes, not listed
  text "1" at -1285.16,5936.5 h70
  text "2" at 1210.5,5936.5 h70
  text "3" at 3699.84,5936.5 h70
  text "4" at 6206.51,5936.5 h70
  text "5" at 8705.5,5936.5 h70
  text "6" at 11210.5,5936.5 h70
  text "A" at -2441.5,4793.5 h70
  text "A" at 12358.5,4793.5 h70
  text "B" at -2441.5,2413.5 h70
  text "B" at 12358.5,2413.5 h70
  text "C" at -2441.5,38.5 h70
  text "C" at 12358.5,38.5 h70
  text "PROJECT TITLE:" at 9318.5,-1822.5 h45
  text ".PRJ_Title" at 9368.5,-1955.83 h70
  text "DESIGNED FOR:" at 9318.5,-2123.5 h45
  text ".PRJ_Customer" at 9368.5,-2263.5 h70
  text "D" at -2441.5,-2331.5 h70
  text "D" at 12358.5,-2331.5 h70
  text "FILE NAME:" at 9318.5,-2423.5 h45
  text ".PCB_File_Name_No_Path" at 9368.5,-2543.5 h70
  text "Texas Instruments (TI) and/or its licensors do not warrant the accuracy or completeness of this specification" at 4349,-2705.34 h45
  text "ENGINEER:" at 9318.5,-2713.5 h45
  text "LAYOUT BY:" at 10823.5,-2713.5 h45
  text "or any information contained therein. TI and/or its licensors do not warrant that this design will meet" at 4304.01,-2818 h45
  text ".PRJ_Engineer" at 9368.5,-2868.49 h70
  text ".PCB_Layout" at 10874,-2868.49 h70
  text "the specifications, will be suitable for your application or fit for any particular purpose, or will operate in" at 4304.01,-2930.67 h45
  text ".Layer_Name" at -1448,-2958.49 h60
  text "ALTIUM DESIGNER VERSION:" at 10823.5,-3023.5 h45
  text "an implementation. TI and/or its licensors do not warrant that the design is production worthy. You should" at 4304.01,-3043.33 h45
  text "completely validate and test your design implementation to confirm the system functionality for your application." at 4349,-3156 h45
  text ".print_Scale" at 9368.5,-3156.83 h70
  text ".Application_BuildNumber" at 10874,-3156.83 h70
  text "1" at -1285.16,-3363.5 h70
  text "2" at 1210.5,-3363.5 h70
  text "3" at 3699.84,-3363.5 h70
  text "4" at 6206.51,-3363.5 h70
  text "5" at 8705.5,-3363.5 h70
  text "6" at 11210.5,-3363.5 h70
M10 Fab Notes:
  drawing of 185 lines, arcs and shapes, not listed
  text "DESIGN INFORMATION" at 10356.02,3810 h60
  text "MIN. TRACK WIDTH:" at 9711.46,3630 h60
  text "8" at 10807.7,3630 h60
  text "MIL" at 10962.46,3630 h60
  text "MIN. CLEARANCE:" at 9711.46,3498 h60
  text "6" at 10747.7,3498 h60
  text "MIL" at 10962.46,3498 h60
  text "MIN. VIA PAD SIZE:" at 9711.46,3366 h60
  text "18" at 10777.71,3366 h60
  text "MIL" at 10962.46,3366 h60
  text "0.05mm (2MIL)" at 10406.46,3224.29 h60
  text "MINIMUM ANNULAR RING" at 9382.23,3220 h60
  text "EXTERNAL" at 11114.46,3220 h60
  text "PER" at 9582.23,3102 h60
  text "IPC-D-275 CLASS 2 LEVEL C" at 9802.23,3102 h60
  text "MIL, HOLES" at 11290.46,2989.71 h60
  text "+/-" at 10898,2989 h60
  text "+/-" at 11752,2989 h60
  text "REGISTRATION TOLERANCES:" at 9382.23,2984 h60
  text "METAL" at 10582,2984 h60
  text "5" at 11158.2,2984 h60
  text "3" at 11991.2,2984 h60
  text "MIL" at 12107.46,2984 h60
  text "MATERIAL:" at 9307.46,2774.54 h60
  text "FR-4 High Tg" at 10293.9,2634.21 h60
  text "FR-408" at 9728.46,2625.64 h60
  text "X" at 10140.46,2625.64 h60
  text "OTHER" at 11216.46,2625.64 h60
  text "63 MIL (1.6mm) +/-10%" at 10048.56,2462.92 h60
  text "THICKNESS:" at 9382.23,2458.64 h60
  text "X" at 9920.4,2458.64 h60
  text "OTHER" at 11333.46,2458.64 h60
  text "TOLERANCE:" at 9382.23,2300.64 h60
  text "X" at 10221.53,2300.64 h60
  text "ANSI IPC-6012 TYPE 3 CLASS 2" at 10408.48,2300.64 h60
  text "OTHER +/-" at 10408.46,2144.64 h60
  text "BOW & TWIST:" at 9382.23,1987.64 h60
  text "X" at 10221.53,1987.64 h60
  text "ANSI IPC-6012 TYPE 3 CLASS 2" at 10408.48,1987.64 h60
  text "OTHER +/-" at 10408.46,1829.13 h60
  text "DRILLING:" at 9307.46,1690.64 h60
  text "REFERENCE:" at 9382.23,1573.64 h60
  text "X" at 10030.46,1573.64 h60
  text "AS SHOWN" at 10217.46,1573.64 h60
  text "X" at 10931.46,1573.64 h60
  text "NC_DRILL FILES" at 11068.46,1573.64 h60
  text "PTH MIN COPPER THICKNESS:" at 9382.23,1415.64 h60
  text "X" at 10732.46,1415.64 h60
  text "1MIL" at 10869.46,1415.64 h60
  text "OTHER" at 11366.46,1415.64 h60
  text "BOARD FINISH:" at 9307.46,1256.64 h60
  text "SILKSCREEN:" at 9462.68,1138.64 h60
  text "X" at 10411.46,1138.64 h60
  text "TOP" at 10537.46,1138.64 h60
  text "X" at 10921.46,1138.64 h60
  text "BOTTOM" at 11048.46,1138.64 h60
  text "SILKSCREEN COLOR:" at 9462.68,971.64 h60
  text "X" at 10410.42,971.64 h60
  text "WHITE" at 10537.46,971.64 h60
  text "OTHER" at 11048.46,971.64 h60
  text "SOLDER RESIST COLOR:" at 9462.68,801.64 h60
  text "X" at 10030.42,642.44 h60
  text "GREEN" at 10157.46,642.44 h60
  text "BLUE" at 10748.46,642.44 h60
  text "OTHER" at 11286.46,642.44 h60
  text "IMMERSION GOLD (ENIG)" at 10368.46,453.92 h60
  text "ENEPIG" at 11706,450.64 h60
  text "SURFACE FINISH:" at 9307.46,449.64 h60
  text "X" at 10181.51,449.64 h60
  text "IMM. TIN/SILVER OR EQUIV" at 9637,292.64 h60
  text "OTHER" at 11068.46,292.64 h60
  text "ARRAY/PANEL:" at 9307.46,113.64 h60
  text "CUT AND TRIM PER MECH LAYER 1" at 10368.46,109.35 h60
  text "N.C. ROUTE" at 10368.46,-42.36 h60
  text "X" at 11047.46,-42.36 h60
  text "V. SCORE" at 11234.46,-42.36 h60
  text "CERTIFICATION:" at 9307.46,-179.36 h60
  text "MATERIALS AND WORKMANSHIP FOR ALL PCBS" at 10032.46,-179.36 h60
  text "TO MEET OR EXCEED THE REQUIREMENTS OF:" at 10032.46,-277.36 h60
  text "X" at 9658.96,-413.87 h60
  text "ANSI IPC-A-600F CLASS ->" at 9797.96,-413.87 h60
  text "X" at 11437.02,-413.87 h60
  text "2" at 11555.96,-413.86 h60
  text "1" at 11240.96,-415.36 h60
  text "3" at 11909.96,-415.36 h60
  text "X" at 9661.02,-573.36 h60
  text "UL 94V-0" at 9797.96,-573.36 h60
  text "X" at 10473.02,-573.36 h60
  text "RoHS" at 10609.96,-573.36 h60
  text "OTHER" at 11254.36,-573.36 h60
  text "PER ORDER" at 11651.42,-573.36 h60
  text "ADDITIONAL REQUIREMENTS:" at 9307.46,-714.36 h60
  text "MICROSECTION:" at 9382.23,-829.36 h60
  text "YES" at 10287.96,-829.36 h60
  text "REQUIRED" at 11149.46,-985.51 h60
  text "BARE BOARD ELEC. TEST:" at 9382.23,-988.36 h60
  text "NONE" at 10687.96,-988.36 h60
  text "X" at 11022.46,-988.36 h60
  text "PER ORDER" at 11741.46,-988.36 h60
  text "MANUFACTURER'S UL:" at 9382.23,-1145.36 h60
  text "RAIL" at 10547.96,-1149.65 h60
  text "METAL" at 11039.77,-1149.65 h60
  text "X" at 11415,-1150 h60
  text "SILK" at 11551.46,-1149.65 h60
  text ".Layer_Name" at -1448,-2958.49 h60
M11 Gerber Information:
  lines w10: -2317,-3030.17 4283,-3030.17 ; -2317,-2826.83 4285,-2826.83 ; -2317,-2623.5 -2317,-3233.5 1688,-3233.5 4285,-3233.5 4285,-2623.5 -2316.5,-2623.5 -2316.5,-3233.5 -741,-3233.5 ; 148,-3233.5 148,-2623.5 ; 1415,-2826.83 1415,-2623.5 ; 2255,-2826.83 2255,-2623.5 ; 2877,-3240 2877,-3037.17
  text "ALL ARTWORK VIEWED FROM TOP SIDE" at -2253.5,-2755.67 h60
  text "BOARD #:" at 223,-2755.67 h60
  text ".PRJ_Number" at 768.5,-2755.67 h60
  text "REV:" at 1613,-2755.67 h60
  text ".PCB_Rev" at 1904.5,-2755.67 h60
  text "SVN REV:" at 2451,-2755.67 h60
  text ".VersionControl_RevNumber" at 2957,-2755.67 h60
  text "LAYER NAME =" at -2253.5,-2958.49 h60
  text "TID #:" at 223,-2959 h60
  text ".TID" at 768.5,-2959 h60
  text "PLOT NAME =" at -2253.5,-3164.34 h60
  text ".plot_File_Name" at -1448,-3164.34 h60
  text "GENERATED    :" at 225,-3164.34 h60
  text ".Print_Date" at 1094.5,-3164.34 h60
  text ".Print_Time" at 1823.5,-3164.34 h60
  text "TEXAS INSTRUMENTS" at 3088,-3164.34 h60
M12 Stackup:
  drawing of 399 lines, arcs and shapes, not listed
  text "Layer" at 4000.09,1955 h60
  text "Name" at 4410,1955 h60
  text "Material" at 5349.74,1955 h60
  text "Thickness" at 6209.51,1955 h60
  text "Constant" at 6859.34,1955 h60
  text "Board Layer Stack" at 7429.2,1955 h60
  text "Top Overlay" at 4410,1835 h60
  text "Top Solder" at 4410,1715 h60
  text "Solder Resist" at 5349.74,1715 h60
  text "0.40mil" at 6209.51,1715 h60
  text "3.5" at 6859.34,1715 h60
  text "1" at 4000.09,1595 h60
  text "Top Layer" at 4410,1595 h60
  text "2.80mil" at 6209.51,1595 h60
  text "Dielectric1" at 4410,1475 h60
  text "FR-4 High TG" at 5349.74,1475 h60
  text "5.00mil" at 6209.51,1475 h60
  text "4.2" at 6859.34,1475 h60
  text "2" at 4000.09,1355 h60
  text "Layer 2" at 4410,1355 h60
  text "2.76mil" at 6209.51,1355 h60
  text "Dielectric 1" at 4410,1235 h60
  text "PP-006" at 5349.74,1235 h60
  text "5.00mil" at 6209.51,1235 h60
  text "4.1" at 6859.34,1235 h60
  text "3" at 4000.09,1115 h60
  text "Signal Layer 3" at 4410,1115 h60
  text "2.80mil" at 6209.51,1115 h60
  text "Dielectric 2" at 4410,995 h60
  text "FR-4 High TG" at 5349.74,995 h60
  text "25.00mil" at 6209.51,995 h60
  text "4.2" at 6859.34,995 h60
  text "4" at 4000.09,875 h60
  text "Signal Layer 4" at 4410,875 h60
  text "2.80mil" at 6209.51,875 h60
  text "Dielectric 4" at 4410,755 h60
  text "PP-006" at 5349.74,755 h60
  text "5.00mil" at 6209.51,755 h60
  text "4.1" at 6859.34,755 h60
  text "5" at 4000.09,635 h60
  text "Layer 5" at 4410,635 h60
  text "2.76mil" at 6209.51,635 h60
  text "Dielectric 3" at 4410,515 h60
  text "FR-4 High TG" at 5349.74,515 h60
  text "5.00mil" at 6209.51,515 h60
  text "4.2" at 6859.34,515 h60
  text "6" at 4000.09,395 h60
  text "Bottom Layer" at 4410,395 h60
  text "2.80mil" at 6209.51,395 h60
  text "Bottom Solder" at 4410,275 h60
  text "Solder Resist" at 5349.74,275 h60
  text "0.40mil" at 6209.51,275 h60
  text "3.5" at 6859.34,275 h60
  text "Bottom Overlay" at 4410,155 h60
  text ".Layer_Name" at -1448,-2958.49 h60
M13 Component Bodies Top:
  text ".Layer_Name" at -1448,-2958.49 h60
M14 Component Bodies Bottom:
  text ".Layer_Name" at -1448,-2958.49 h60
M15 Courtyards Top:
  text ".Layer_Name" at -1448,-2958.49 h60
M16 Courtyards Bottom:
  text ".Layer_Name" at -1448,-2958.49 h60
Drill Drawing:
  circle w10: c4070.62,-1499.17 r33.33
  lines w10: 4037.29,-1665.83 4053.96,-1665.83 4070.62,-1682.5 4087.29,-1665.83 4103.96,-1665.83 4087.29,-1649.17 4103.96,-1632.5 4087.29,-1632.5 4070.62,-1615.83 4053.96,-1632.5 4037.29,-1632.5 4053.96,-1649.17 4037.29,-1665.83 ; 4037.29,-1315.83 4103.96,-1315.83 4070.62,-1382.5 4037.29,-1315.83 ; 4037.29,-1232.5 4070.62,-1215.83 4103.96,-1232.5 4087.29,-1199.17 4103.96,-1165.83 4070.62,-1182.5 4037.29,-1165.83 4053.96,-1199.17 4037.29,-1232.5 ; 4037.29,-1082.5 4037.29,-1065.83 4053.96,-1049.17 4037.29,-1032.5 4037.29,-1015.83 4053.96,-1015.83 4070.62,-1032.5 4087.29,-1015.83 4103.96,-1015.83 4103.96,-1032.5 4087.29,-1049.17 4103.96,-1065.83 4103.96,-1082.5 4087.29,-1082.5 4070.62,-1065.83 4053.96,-1082.5 4037.29,-1082.5 ; 4037.29,-932.5 4103.96,-932.5 4103.96,-865.83 4037.29,-865.83 4037.29,-932.5
  lines w15: 3977.5,-1727.5 7856.47,-1727.5 ; 3977.5,-827.5 7856.47,-827.5 ; 4528.38,-1877.5 4528.38,-677.5 ; 5226.19,-1877.5 5226.19,-677.5 ; 6571.79,-1877.5 6571.79,-677.5 ; 7077.67,-1877.5 7077.67,-677.5 ; 3977.5,-1877.5 7856.47,-1877.5 7856.47,-677.5 3977.5,-677.5 3977.5,-1877.5
  text "Symbol" at 4067.5,-782.5 h72
  text "Hit Count" at 4573.38,-782.5 h72
  text "Finished Hole Size" at 5271.19,-782.5 h72
  text "Plated" at 6616.79,-782.5 h72
  text "Hole Type" at 7122.67,-782.5 h72
  text "4" at 4573.38,-932.5 h60
  text "40.00mil (1.016mm)" at 5271.19,-932.5 h60
  text "PTH" at 6616.79,-932.5 h60
  text "Round" at 7122.67,-932.5 h60
  text "4" at 4573.38,-1082.5 h60
  text "40.16mil (1.020mm)" at 5271.19,-1082.5 h60
  text "PTH" at 6616.79,-1082.5 h60
  text "Round" at 7122.67,-1082.5 h60
  text "6" at 4573.38,-1232.5 h60
  text "49.21mil (1.250mm)" at 5271.19,-1232.5 h60
  text "PTH" at 6616.79,-1232.5 h60
  text "Round" at 7122.67,-1232.5 h60
  text "8" at 4573.38,-1382.5 h60
  text "63.00mil (1.600mm)" at 5271.19,-1382.5 h60
  text "PTH" at 6616.79,-1382.5 h60
  text "Round" at 7122.67,-1382.5 h60
  text "22" at 4573.38,-1532.5 h60
  text "7.87mil (0.200mm)" at 5271.19,-1532.5 h60
  text "PTH" at 6616.79,-1532.5 h60
  text "Round" at 7122.67,-1532.5 h60
  text "560" at 4573.38,-1682.5 h60
  text "10.00mil (0.254mm)" at 5271.19,-1682.5 h60
  text "PTH" at 6616.79,-1682.5 h60
  text "Round" at 7122.67,-1682.5 h60
  text "604 Total" at 4573.38,-1832.5 h60
  text ".Layer_Name" at -1448,-2958.49 h60

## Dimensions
-1500,1000 to -1500,-1000 on M2 Board Dimensions
1500,-1000 to -1500,-1000 on M2 Board Dimensions
-675,375 to -680,-375 on M2 Board Dimensions
525,405 to -625,405 on M2 Board Dimensions
-2025,-2500 to -1025,-2500 on M2 Board Dimensions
